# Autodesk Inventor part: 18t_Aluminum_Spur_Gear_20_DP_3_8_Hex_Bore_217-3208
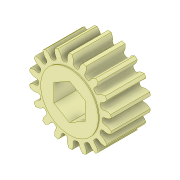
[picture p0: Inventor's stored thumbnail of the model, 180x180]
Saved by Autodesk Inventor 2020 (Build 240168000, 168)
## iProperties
Created: 2013-12
Part Number: 18t_Aluminum_Spur_Gear_20_DP_3_8_Hex_Bore_217-3208
Material: Aluminum 6061
Description: STEP AP214
Document SubType Name: Modeling
Designer: Kevin
Density: 2.7 g/cm^3
Appearance: Aluminum - Flat
Mass: 10.5696 g
Surface Area: 28.4471 cm^2
Volume: 3.91467 cm^3
Vendor: VEX
Sending System: SolidWorks 2013
Preprocessor: SwSTEP 2.0
Title: 217-3208-STEP.STEP
Revision Number: ANY
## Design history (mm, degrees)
feature "Cut-Extrude2"
body "Solid1"
